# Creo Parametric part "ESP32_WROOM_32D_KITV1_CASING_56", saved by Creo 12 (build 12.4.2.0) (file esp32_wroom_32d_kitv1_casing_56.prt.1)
Units: Custom; MM, KILOGRAM, SECS

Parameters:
  PTC_WM_ITERATION = "0"
  PTC_WM_VERSION = "-.0"
  PTC_WM_LIFECYCLE_STATE = "In Work"
  PTC_WM_LIFECYCLE = "MO_CADDocument"
  PTC_WM_CREATED_BY = "Maximilian Roepper (Z0017RMS: MO)"
  PTC_WM_CREATED_ON = "18-Sep-26 11:36:42 AM"
  PTC_WM_MODIFIED_BY = "Maximilian Roepper (Z0017RMS: MO)"
  PTC_WM_MODIFIED_ON = "18-Sep-26 11:36:46 AM"
  PDMLINKNUMBER = "PDM000071455266"
  PTC_WM_NAME = "esp32_wroom_32d_kitv1_casing_56.prt"
  PTC_WM_NUMBER = "PDM000071455266"

Other parameters: WEIGHT, WEIGHT_FACTOR, WEIGHT_ADD, _MASS_TEMP, _DIFF_TEMP, MC_ERRORS, SUPPLIER

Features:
  1. coordinate system
  2. datum plane "PRT_YZ"
  3. datum plane "PRT_XY"
  4. datum plane "PRT_XZ"
  5. coordinate system
  6. datum axis
  7. datum axis
  8. datum axis
  9. coordinate system
  10. imported feature
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
Other named items: PRT, SIEMENS_MO, DRW_VIEW_ORG, PRT_X, PRT_Y, PRT_Z, CS0, ROUGH_GROB

Layers: 00_STD_CSYS-KSYS, 01_STD_PLANES-EBENEN, 02_STD_AXES-ACHSEN, 03_STD_CSYS-KSYS, 24_IMPORT_FEAT-IMPORT_KE

Surfaces: 5 plane, 1 cylinder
